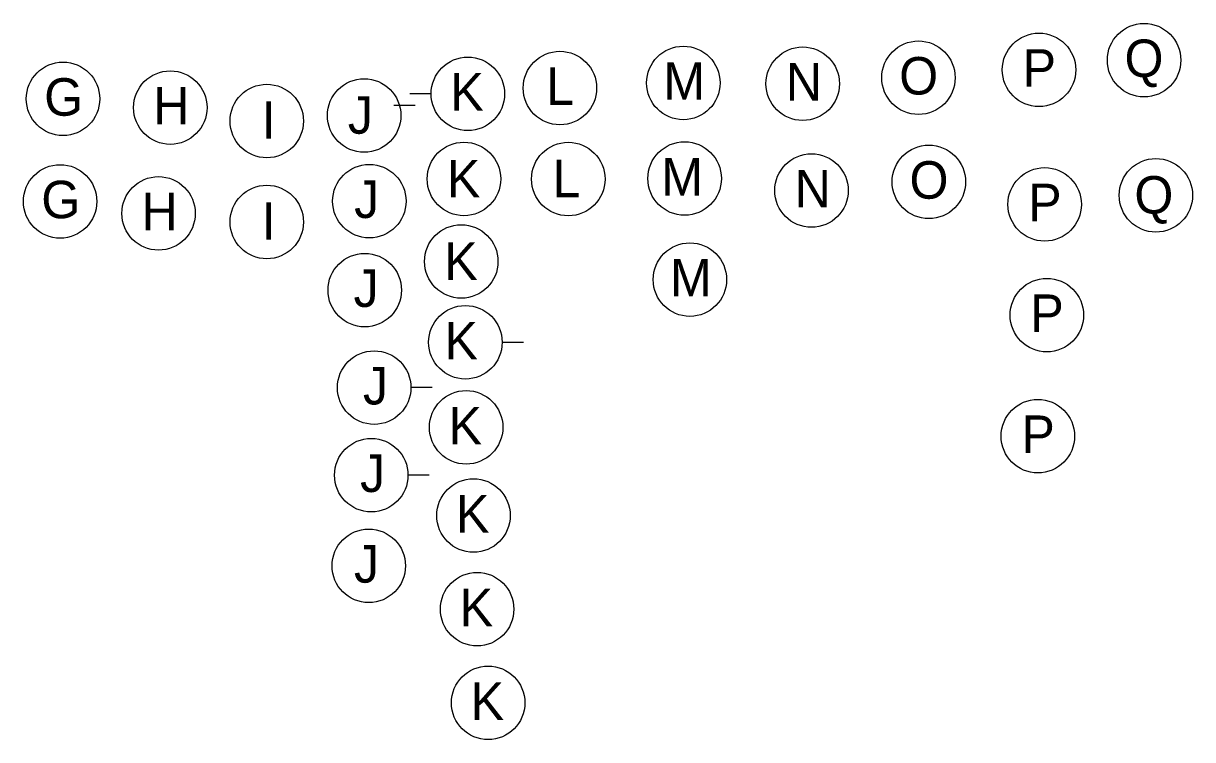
# Model space of a CAD drawing. Extents: x 2157572 to 5059327, y 715220 to 1674494.
# Drawn here: x 2163711 to 2165895, y 731419 to 732756 of the extents above; entities that cross this region are included whole.
import ezdxf

# ---------------------------------------------------------------- set-up
doc = ezdxf.new("R2010")
doc.units = 0
for name, color, linetype in [('Exist Cultural Church Label', 7, 'Continuous'), ('Exist Road Primary US Structure Standard Bridge Number Label', 7, 'Continuous'), ('Level 51', 7, 'Continuous'), ('Map Preparation County Base Legend Highway Garage or Maintenance Office', 7, 'Continuous')]:
    doc.layers.add(name, color=color, linetype=linetype)

msp = doc.modelspace()

# ---------------------------------------------------------------- linework, layer by layer
at = {"layer": 'Exist Cultural Church Label'}
for centre in [(2165608.5, 732669.2), (2165804.7, 732687.3), (2164944.1, 732644.8), (2165383.3, 732654.6), (2164541.6, 732624.5), (2164713.6, 732635.3), (2165167.1, 732643.4), (2163785.4, 732615.2), (2163985.8, 732598.8), (2164347.9, 732584.1), (2164166, 732573.8), (2164534.3, 732465.7), (2164729.2, 732465.5), (2164946.5, 732466.5), (2165402.7, 732460.2), (2165183.5, 732444), (2165826.8, 732435.1), (2163780, 732423.7), (2164357.6, 732424.2), (2165619, 732418.2), (2163963.9, 732401.4), (2164166, 732385.3), (2164529.3, 732311.7), (2164956.4, 732277.8), (2164349, 732258.2), (2165623.1, 732211.5), (2164537, 732160.8), (2164366.6, 732076.2), (2164538.4, 732002.1), (2165606.3, 731985.6), (2164361.2, 731912.8), (2164552.1, 731837.5), (2164356.5, 731743.6), (2164558.9, 731662.7), (2164579.5, 731487.9)]:
    msp.add_circle(centre, 68.6, dxfattribs=at)
at = {"layer": 'Level 51'}
for p, q in [((2164473, 732624.5), (2164433.4, 732624.5)), ((2164403.4, 732603.1), (2164443, 732603.1)), ((2164605.7, 732160.8), (2164645.3, 732160.8)), ((2164474.9, 732076.2), (2164435.3, 732076.2)), ((2164469.4, 731912.8), (2164429.8, 731912.8))]:
    msp.add_line(p, q, dxfattribs=at)
at = {"layer": 'Map Preparation County Base Legend Highway Garage or Maintenance Office'}
for centre in [(2165608.5, 732669.2), (2165804.7, 732687.3), (2164944.1, 732644.8), (2165383.3, 732654.6), (2164541.6, 732624.5), (2164713.6, 732635.3), (2165167.1, 732643.4), (2163785.4, 732615.2), (2163985.8, 732598.8), (2164347.9, 732584.1), (2164166, 732573.8), (2164534.3, 732465.7), (2164729.2, 732465.5), (2164946.5, 732466.5), (2165402.7, 732460.2), (2165183.5, 732444), (2165826.8, 732435.1), (2163780, 732423.7), (2164357.6, 732424.2), (2165619, 732418.2), (2163963.9, 732401.4), (2164166, 732385.3), (2164529.3, 732311.7), (2164956.4, 732277.8), (2164349, 732258.2), (2165623.1, 732211.5), (2164537, 732160.8), (2164366.6, 732076.2), (2164538.4, 732002.1), (2165606.3, 731985.6), (2164361.2, 731912.8), (2164552.1, 731837.5), (2164356.5, 731743.6), (2164356.5, 731743.6), (2164558.9, 731662.7), (2164579.5, 731487.9)]:
    msp.add_circle(centre, 68.6, dxfattribs=at)

# ---------------------------------------------------------------- texts
at = {"layer": 'Exist Cultural Church Label'}
for s, p in [('L', (2164699.9, 732431.4)), ('Q', (2165786.6, 732401))]:
    msp.add_text(s, height=70, dxfattribs=at).set_placement(p)
at = {"layer": 'Exist Road Primary US Structure Standard Bridge Number Label'}
for s, p in [('Q', (2165768.2, 732655.9)), ('O', (2165347.3, 732623.2)), ('P', (2165577.8, 732637.8)), ('L', (2164687.9, 732603.9)), ('M', (2164906.8, 732613.4)), ('N', (2165135.6, 732612)), ('G', (2163750.2, 732583.7)), ('K', (2164508.8, 732593.1)), ('H', (2163954.2, 732567.4)), ('J', (2164317.5, 732550.1)), ('K', (2164502.5, 732431.3)), ('M', (2164902.9, 732434.5)), ('O', (2165366.6, 732428.8)), ('N', (2165152, 732412.6)), ('G', (2163744.8, 732392.3)), ('J', (2164329.2, 732392.8)), ('P', (2165588.3, 732386.8)), ('H', (2163932.3, 732370)), ('K', (2164497.5, 732277.3)), ('M', (2164919.1, 732246.4)), ('J', (2164328.1, 732226.8)), ('P', (2165592.3, 732180.1)), ('K', (2164498, 732128.8)), ('J', (2164345.7, 732044.8)), ('K', (2164505.7, 731970.2)), ('P', (2165575.6, 731954.2)), ('J', (2164340.3, 731881.4)), ('K', (2164519.4, 731805.7)), ('J', (2164328.9, 731712.2)), ('K', (2164526.3, 731630.9)), ('K', (2164546.8, 731456.1))]:
    msp.add_text(s, height=70, dxfattribs=at).set_placement(p)
for p in [(2164156.3, 732540.6), (2164156.3, 732352.1)]:
    msp.add_text('I', height=70, rotation=360, dxfattribs=at).set_placement(p)

doc.saveas('drawing.dxf')
